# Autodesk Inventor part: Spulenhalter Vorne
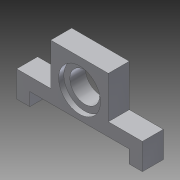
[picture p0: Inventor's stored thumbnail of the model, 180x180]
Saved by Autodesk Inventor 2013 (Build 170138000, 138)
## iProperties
Created: 2013-02
Part Number: Spulenhalter Vorne
Material: Aluminium 6061
Document SubType Name: Modeling
Designer: rYan
Mass: 25.8426 g
Surface Area: 43.2499 cm^2
Volume: 9.53601 cm^3
Density: 2.71 g/cm^3
Author: rYan
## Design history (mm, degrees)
sketch "Skizze1"
  geometry: L1 (-11, 26)-(11, 26); L2 (25, 10)-(25, 0); L3 (25, 0)-(20, 0); L4 (20, 0)-(20, 5); L5 (20, 5)-(-20, 5); L6 (-20, 5)-(-20, 0); L7 (-25, 10)-(-25, 0); L8 (-25, 0)-(-20, 0); L9 (0, -5.2)-(0, 31.2) reference; L10 (-35, 0)-(35, 0) reference; L11 (-25, 10)-(-11, 10); L12 (-11, 10)-(-11, 26); L13 (25, 10)-(11, 10); L14 (11, 10)-(11, 26); 1 further point
  constraints: 24 end point, 4 parallel, 4 perpendicular, 1 collinear, 5 other
  dimensions: "d0" = 40 distance of L4.end L5.end; "d2" = 5 distance of L7.end L6.end; "d4" = 5 distance of L5.end L6.end; "d23" = 10 distance of L7.start L7.end; "d24" = 16 distance of L11.end L1.start; "d25" = 22 distance of L1.start L1.end
extrude "Extrusion1" new body sketch "Skizze1" distance "d5" = 8; taper "d6" = 0 deg
sketch "Skizze2"
  geometry: L1 (-25, 0)-(-25, 10) reference; L2 (25, 10)-(25, 0) reference; L3 (20, 5)-(-20, 5) reference; L4 (0, 26)-(0, 5); L5 (25, 0)-(20, 0) reference; 2 further points; 1 other entity
  constraints: 2 end point, 1 midpoint, 1 point on line, 2 other
  dimensions: "d26" = 15 distance from line of L5 point (0, 15)
hole "Bohrung1" sketch "Skizze2" at (0, 15) diameter "d8" = 11.4; stored, may be unused: countersink angle "d12" = 90 deg, drill point angle "d14" = 118 deg; dims "d9" = 6, "d10" = 16, "d11" = 2, "d13" = 8
sketch "Skizze3"
  geometry: L1 (0, 0)-(5, 0) reference; L2 (5, 0)-(5, 8) reference; L3 (0, 8)-(5, 8) reference; L4 (0, 0)-(0, 8) reference; L5 (0, 4)-(5, 4); 2 further points
  constraints: 3 midpoint, 2 end point
  dimensions: "d15" = 2.5 distance from line of point (2.5, 4) L4
hole "Bohrung2" sketch "Skizze3" at (2.5, 4) diameter "d16" = 3.242; stored, may be unused: countersink angle "d20" = 90 deg, drill point angle "d22" = 118 deg; dims "d17" = 6, "d18" = 16, "d19" = 2, "d21" = 7
mirror "Spiegeln1"
fillet "Rundung2" dims "d28" = 5
fillet "Rundung3" dims "d29" = 4
node "Volumenkörper1"
node "Projizierte Kontur1"
